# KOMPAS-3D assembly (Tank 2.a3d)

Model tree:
1. Plane XY
2. Plane ZX
3. Plane ZY
4. X Axis
5. Y Axis
6. Z Axis
7. Origin
8. Attachment Point:1
9. Attachment Point:2
10. Attachment Point:3  (labels: C:\Program Files\ASCON\KOMPAS-3D V10\Sys\graphic.lyt; Tank 2; Tank 2.spw; Tank 2.a3d)

Referenced files in C:\Documents and Settings\kashirsky\Мои документы\Camtasia Studio\Pipelines3D\Tanks\: Tank 2.m3d, Piping_Flange_50_1000.m3d, Piping_Flange_150_1000.m3d, Tank 2.a3d, Tank 2.spw, Tanks_step 1.a3d, Tanks_step 1.spw, Tanks_step 2.a3d, Tanks_step 3.a3d, Tanks_step 4.a3d
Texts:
  Tank 2
  Three Point Plane
  Plane at Angle
  Line and Point Plane
  Axis through Two Vertices
  Axis of Feature
  Axis of Conical Surface
  Axis through Edge
  Trim by Surface
  Trim by Sketch
  Intersection Axis of Two Planes
  Two Line Plane
  Line and Face Plane
  Pattern by Sample
  Point in CM
  Feature with No History
  Linear Dimension from Line to Point
  Surface Finish Symbol
  Geometric Tolerance Symbol
  Текст на чертеже
  Линия-выноска #1
  Линия-выноска #2
  Линия-выноска #3
  Отклонения формы и база
  Марка координационной оси
  Марка/позиционное обозначение с линией-выноской
  Марка/позиционное обозначение на линии
  Марка/позиционное обозначение без линии-выноски
  Steel ASTM A295
  Flange Dn 50
  Flange Dn 150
